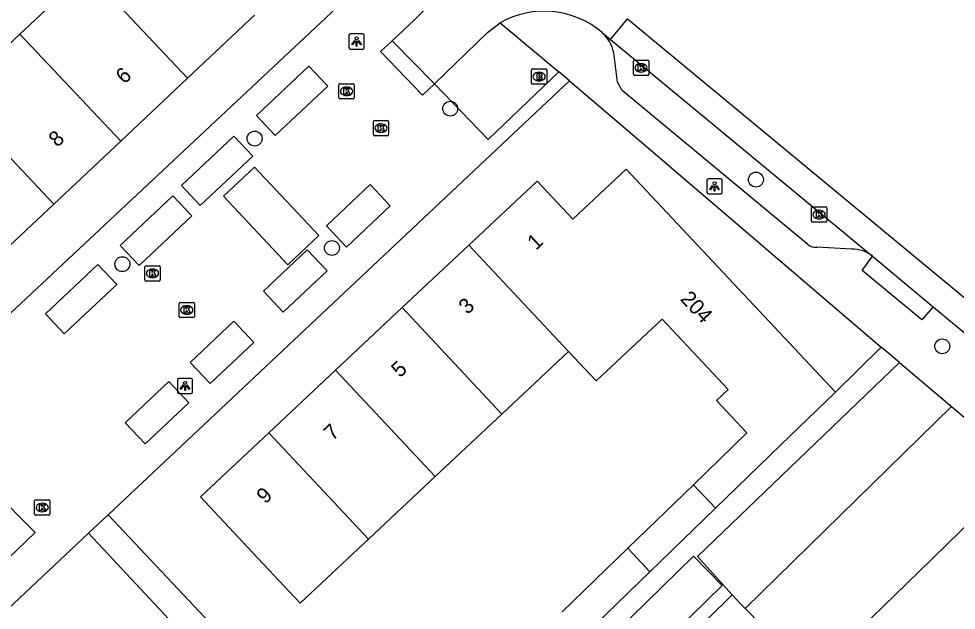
# Model space of a CAD drawing. Extents: x 161882 to 162509, y 381687 to 382379.
# Drawn here: x 162409.8 to 162471.3, y 381838.9 to 381877.6 of the extents above; entities that cross this region are included whole.
import ezdxf

# ---------------------------------------------------------------- set-up
doc = ezdxf.new("R2010")
doc.units = 0
for name, color, linetype in [('IMGEO_Boom', 7, 'Continuous'), ('IMGEO_Brandkraan', 7, 'Continuous'), ('IMGEO_Fietspad_gesloten', 7, 'Continuous'), ('IMGEO_Kolk', 7, 'Continuous'), ('IMGEO_Lichtpunt', 7, 'Continuous'), ('IMGEO_Muur', 7, 'Continuous'), ('IMGEO_Pand', 7, 'Continuous'), ('IMGEO_Pand_nummerreeks', 7, 'Continuous'), ('IMGEO_Parkeervlak_open', 7, 'Continuous'), ('IMGEO_Rijbaan_lokaal_open', 7, 'Continuous'), ('IMGEO_Voetpad_open', 7, 'Continuous')]:
    doc.layers.add(name, color=color, linetype=linetype)

msp = doc.modelspace()

# ---------------------------------------------------------------- linework, layer by layer
at = {"layer": 'IMGEO_Boom'}
for centre in [(162438.129, 381871.741), (162425.306, 381869.781), (162458.161, 381867.092), (162430.377, 381862.605), (162416.641, 381861.547), (162470.374, 381856.157)]:
    msp.add_circle(centre, 0.489, dxfattribs=at)
at = {"layer": 'IMGEO_Brandkraan'}
for p, q in [((162443.452, 381873.418), (162443.452, 381874.27)), ((162443.527, 381874.344), (162444.379, 381874.344)), ((162443.94, 381874.124), (162443.965, 381874.124)), ((162444.453, 381874.27), (162444.453, 381873.418)), ((162444.379, 381873.344), (162443.527, 381873.344)), ((162443.963, 381873.564), (162443.938, 381873.564))]:
    msp.add_line(p, q, dxfattribs=at)
for points in [[(162443.452, 381873.418), (162443.452, 381874.27)], [(162443.527, 381874.344), (162444.379, 381874.344)], [(162443.8, 381874.044), (162443.8, 381873.644), (162444.013, 381873.644)], [(162444.031, 381874.044), (162443.8, 381874.044)], [(162443.979, 381873.963), (162443.925, 381873.963), (162443.925, 381873.887)], [(162443.925, 381873.887), (162443.978, 381873.887)], [(162443.987, 381873.811), (162443.925, 381873.811), (162443.925, 381873.73)], [(162444.453, 381874.27), (162444.453, 381873.418)], [(162444.379, 381873.344), (162443.527, 381873.344)], [(162443.925, 381873.73), (162443.987, 381873.73)]]:
    msp.add_lwpolyline(points, dxfattribs=at)
for centre, radius, start, end in [((162443.529, 381874.268), 0.0765, 91.55205, 178.44795), ((162443.529, 381874.268), 0.0765, 91.55205, 178.44795), ((162443.98, 381873.925), 0.0379, 267.82845, 90.93552), ((162443.988, 381873.77), 0.0404, 269.87594, 90.50774), ((162444.035, 381873.899), 0.145, 59.4692, 91.53667), ((162444.06, 381873.946), 0.0922, 285.51372, 58.15012), ((162444.065, 381873.754), 0.105, 301.31148, 78.98903), ((162444.377, 381874.268), 0.0765, 1.55205, 88.44795), ((162444.377, 381874.268), 0.0765, 1.55205, 88.44795), ((162443.529, 381873.42), 0.0765, 181.55205, 268.44795), ((162443.529, 381873.42), 0.0765, 181.55205, 268.44795), ((162444.019, 381873.895), 0.251, 268.66757, 293.53466), ((162444.377, 381873.42), 0.0765, 271.55205, 358.44795), ((162444.377, 381873.42), 0.0765, 271.55205, 358.44795)]:
    msp.add_arc(centre, radius, start, end, dxfattribs=at)
for centre, major_axis, ratio, start_param, end_param in [((162443.939, 381873.844), (-0.387, 0.002), 0.722429, 4.712389, 7.853982), ((162443.964, 381873.844), (-0.39, 0.002), 0.717154, 1.570796, 4.712389)]:
    msp.add_ellipse(centre, major_axis=major_axis, ratio=ratio, start_param=start_param, end_param=end_param, dxfattribs=at)
at = {"layer": 'IMGEO_Fietspad_gesloten'}
for points in [[(162448.641, 381876.269), (162465.814, 381862.06)], [(162465.814, 381862.06), (162469.781, 381858.758)], [(162469.781, 381858.758), (162474.835, 381854.567)]]:
    msp.add_lwpolyline(points, dxfattribs=at)
at = {"layer": 'IMGEO_Kolk'}
for p, q in [((162450.133, 381873.994), (162450.133, 381874.846)), ((162450.208, 381874.92), (162451.06, 381874.92)), ((162450.621, 381874.7), (162450.646, 381874.7)), ((162451.134, 381874.846), (162451.134, 381873.994)), ((162451.06, 381873.92), (162450.208, 381873.92)), ((162450.644, 381874.14), (162450.619, 381874.14)), ((162430.835, 381872.454), (162430.835, 381873.306)), ((162430.91, 381873.38), (162431.762, 381873.38)), ((162431.836, 381873.306), (162431.836, 381872.454)), ((162431.346, 381872.6), (162431.321, 381872.6)), ((162431.323, 381873.16), (162431.348, 381873.16)), ((162431.762, 381872.38), (162430.91, 381872.38)), ((162433.092, 381870.04), (162433.092, 381870.892)), ((162433.167, 381870.966), (162434.019, 381870.966)), ((162433.58, 381870.746), (162433.605, 381870.746)), ((162434.093, 381870.892), (162434.093, 381870.04)), ((162433.603, 381870.186), (162433.578, 381870.186)), ((162434.019, 381869.966), (162433.167, 381869.966)), ((162461.804, 381864.37), (162461.804, 381865.222)), ((162461.879, 381865.296), (162462.731, 381865.296)), ((162462.805, 381865.222), (162462.805, 381864.37)), ((162462.292, 381865.076), (162462.317, 381865.076)), ((162462.731, 381864.296), (162461.879, 381864.296)), ((162462.315, 381864.516), (162462.29, 381864.516)), ((162418.117, 381860.516), (162418.117, 381861.368)), ((162418.192, 381861.442), (162419.044, 381861.442)), ((162418.605, 381861.222), (162418.63, 381861.222)), ((162419.118, 381861.368), (162419.118, 381860.516)), ((162419.044, 381860.442), (162418.192, 381860.442)), ((162418.628, 381860.662), (162418.603, 381860.662)), ((162420.436, 381859.042), (162421.288, 381859.042)), ((162420.361, 381858.116), (162420.361, 381858.968)), ((162420.849, 381858.822), (162420.874, 381858.822)), ((162421.362, 381858.968), (162421.362, 381858.116)), ((162421.288, 381858.042), (162420.436, 381858.042)), ((162420.872, 381858.262), (162420.847, 381858.262)), ((162410.889, 381845.168), (162410.889, 381846.02)), ((162410.964, 381846.094), (162411.816, 381846.094)), ((162411.377, 381845.874), (162411.402, 381845.874)), ((162411.89, 381846.02), (162411.89, 381845.168)), ((162411.816, 381845.094), (162410.964, 381845.094)), ((162411.4, 381845.314), (162411.375, 381845.314))]:
    msp.add_line(p, q, dxfattribs=at)
for points in [[(162450.133, 381873.994), (162450.133, 381874.846)], [(162450.208, 381874.92), (162451.06, 381874.92)], [(162450.454, 381874.62), (162450.577, 381874.62), (162450.577, 381874.469), (162450.707, 381874.62), (162450.871, 381874.62), (162450.725, 381874.469), (162450.878, 381874.22), (162450.726, 381874.22), (162450.641, 381874.384), (162450.577, 381874.317), (162450.577, 381874.22), (162450.454, 381874.22), (162450.454, 381874.62)], [(162451.134, 381874.846), (162451.134, 381873.994)], [(162451.06, 381873.92), (162450.208, 381873.92)], [(162430.835, 381872.454), (162430.835, 381873.306)], [(162430.91, 381873.38), (162431.762, 381873.38)], [(162431.836, 381873.306), (162431.836, 381872.454)], [(162431.156, 381873.08), (162431.279, 381873.08), (162431.279, 381872.929), (162431.409, 381873.08), (162431.573, 381873.08), (162431.427, 381872.929), (162431.58, 381872.68), (162431.428, 381872.68), (162431.343, 381872.844), (162431.279, 381872.777), (162431.279, 381872.68), (162431.156, 381872.68), (162431.156, 381873.08)], [(162431.762, 381872.38), (162430.91, 381872.38)], [(162433.092, 381870.04), (162433.092, 381870.892)], [(162433.167, 381870.966), (162434.019, 381870.966)], [(162434.093, 381870.892), (162434.093, 381870.04)], [(162433.413, 381870.666), (162433.536, 381870.666), (162433.536, 381870.515), (162433.666, 381870.666), (162433.83, 381870.666), (162433.684, 381870.515), (162433.837, 381870.266), (162433.685, 381870.266), (162433.6, 381870.43), (162433.536, 381870.363), (162433.536, 381870.266), (162433.413, 381870.266), (162433.413, 381870.666)], [(162434.019, 381869.966), (162433.167, 381869.966)], [(162461.804, 381864.37), (162461.804, 381865.222)], [(162461.879, 381865.296), (162462.731, 381865.296)], [(162462.805, 381865.222), (162462.805, 381864.37)], [(162462.125, 381864.996), (162462.248, 381864.996), (162462.248, 381864.845), (162462.378, 381864.996), (162462.542, 381864.996), (162462.396, 381864.845), (162462.549, 381864.596), (162462.397, 381864.596), (162462.312, 381864.76), (162462.248, 381864.693), (162462.248, 381864.596), (162462.125, 381864.596), (162462.125, 381864.996)], [(162462.731, 381864.296), (162461.879, 381864.296)], [(162418.117, 381860.516), (162418.117, 381861.368)], [(162418.192, 381861.442), (162419.044, 381861.442)], [(162418.438, 381861.142), (162418.561, 381861.142), (162418.561, 381860.991), (162418.691, 381861.142), (162418.855, 381861.142), (162418.709, 381860.991), (162418.862, 381860.742), (162418.71, 381860.742), (162418.625, 381860.906), (162418.561, 381860.839), (162418.561, 381860.742), (162418.438, 381860.742), (162418.438, 381861.142)], [(162419.118, 381861.368), (162419.118, 381860.516)], [(162419.044, 381860.442), (162418.192, 381860.442)], [(162420.436, 381859.042), (162421.288, 381859.042)], [(162420.361, 381858.116), (162420.361, 381858.968)], [(162420.682, 381858.742), (162420.805, 381858.742), (162420.805, 381858.591), (162420.935, 381858.742), (162421.099, 381858.742), (162420.953, 381858.591), (162421.106, 381858.342), (162420.954, 381858.342), (162420.869, 381858.506), (162420.805, 381858.439), (162420.805, 381858.342), (162420.682, 381858.342), (162420.682, 381858.742)], [(162421.362, 381858.968), (162421.362, 381858.116)], [(162421.288, 381858.042), (162420.436, 381858.042)], [(162410.889, 381845.168), (162410.889, 381846.02)], [(162410.964, 381846.094), (162411.816, 381846.094)], [(162411.21, 381845.794), (162411.333, 381845.794), (162411.333, 381845.643), (162411.463, 381845.794), (162411.627, 381845.794), (162411.481, 381845.643), (162411.634, 381845.394), (162411.482, 381845.394), (162411.397, 381845.558), (162411.333, 381845.491), (162411.333, 381845.394), (162411.21, 381845.394), (162411.21, 381845.794)], [(162411.89, 381846.02), (162411.89, 381845.168)], [(162411.816, 381845.094), (162410.964, 381845.094)]]:
    msp.add_lwpolyline(points, dxfattribs=at)
for centre, start, end in [((162450.21, 381874.844), 91.55205, 178.44795), ((162450.21, 381874.844), 91.55205, 178.44795), ((162451.058, 381874.844), 1.55205, 88.44795), ((162451.058, 381874.844), 1.55205, 88.44795), ((162450.21, 381873.996), 181.55205, 268.44795), ((162450.21, 381873.996), 181.55205, 268.44795), ((162451.058, 381873.996), 271.55205, 358.44795), ((162451.058, 381873.996), 271.55205, 358.44795), ((162430.912, 381873.304), 91.55205, 178.44795), ((162430.912, 381873.304), 91.55205, 178.44795), ((162431.76, 381873.304), 1.55205, 88.44795), ((162431.76, 381873.304), 1.55205, 88.44795), ((162430.912, 381872.456), 181.55205, 268.44795), ((162430.912, 381872.456), 181.55205, 268.44795), ((162431.76, 381872.456), 271.55205, 358.44795), ((162431.76, 381872.456), 271.55205, 358.44795), ((162433.169, 381870.89), 91.55205, 178.44795), ((162433.169, 381870.89), 91.55205, 178.44795), ((162434.017, 381870.89), 1.55205, 88.44795), ((162434.017, 381870.89), 1.55205, 88.44795), ((162433.169, 381870.042), 181.55205, 268.44795), ((162433.169, 381870.042), 181.55205, 268.44795), ((162434.017, 381870.042), 271.55205, 358.44795), ((162434.017, 381870.042), 271.55205, 358.44795), ((162461.881, 381865.22), 91.55205, 178.44795), ((162461.881, 381865.22), 91.55205, 178.44795), ((162462.729, 381865.22), 1.55205, 88.44795), ((162462.729, 381865.22), 1.55205, 88.44795), ((162461.881, 381864.372), 181.55205, 268.44795), ((162461.881, 381864.372), 181.55205, 268.44795), ((162462.729, 381864.372), 271.55205, 358.44795), ((162462.729, 381864.372), 271.55205, 358.44795), ((162418.194, 381861.366), 91.55205, 178.44795), ((162418.194, 381861.366), 91.55205, 178.44795), ((162419.042, 381861.366), 1.55205, 88.44795), ((162419.042, 381861.366), 1.55205, 88.44795), ((162418.194, 381860.518), 181.55205, 268.44795), ((162418.194, 381860.518), 181.55205, 268.44795), ((162419.042, 381860.518), 271.55205, 358.44795), ((162419.042, 381860.518), 271.55205, 358.44795), ((162420.438, 381858.966), 91.55205, 178.44795), ((162420.438, 381858.966), 91.55205, 178.44795), ((162421.286, 381858.966), 1.55205, 88.44795), ((162421.286, 381858.966), 1.55205, 88.44795), ((162420.438, 381858.118), 181.55205, 268.44795), ((162420.438, 381858.118), 181.55205, 268.44795), ((162421.286, 381858.118), 271.55205, 358.44795), ((162421.286, 381858.118), 271.55205, 358.44795), ((162410.966, 381846.018), 91.55205, 178.44795), ((162410.966, 381846.018), 91.55205, 178.44795), ((162411.814, 381846.018), 1.55205, 88.44795), ((162411.814, 381846.018), 1.55205, 88.44795), ((162410.966, 381845.17), 181.55205, 268.44795), ((162410.966, 381845.17), 181.55205, 268.44795), ((162411.814, 381845.17), 271.55205, 358.44795), ((162411.814, 381845.17), 271.55205, 358.44795)]:
    msp.add_arc(centre, 0.0765, start, end, dxfattribs=at)
for centre, major_axis, ratio, start_param, end_param in [((162450.62, 381874.42), (-0.387, 0.002), 0.722429, 4.712389, 7.853982), ((162450.645, 381874.42), (-0.39, 0.002), 0.717154, 1.570796, 4.712389), ((162431.322, 381872.88), (-0.387, 0.002), 0.722429, 4.712389, 7.853982), ((162431.347, 381872.88), (-0.39, 0.002), 0.717154, 1.570796, 4.712389), ((162433.579, 381870.466), (-0.387, 0.002), 0.722429, 4.712389, 7.853982), ((162433.604, 381870.466), (-0.39, 0.002), 0.717154, 1.570796, 4.712389), ((162462.291, 381864.796), (-0.387, 0.002), 0.722429, 4.712389, 7.853982), ((162462.316, 381864.796), (-0.39, 0.002), 0.717154, 1.570796, 4.712389), ((162418.604, 381860.942), (-0.387, 0.002), 0.722429, 4.712389, 7.853982), ((162418.629, 381860.942), (-0.39, 0.002), 0.717154, 1.570796, 4.712389), ((162420.848, 381858.542), (-0.387, 0.002), 0.722429, 4.712389, 7.853982), ((162420.873, 381858.542), (-0.39, 0.002), 0.717154, 1.570796, 4.712389), ((162411.376, 381845.594), (-0.387, 0.002), 0.722429, 4.712389, 7.853982), ((162411.401, 381845.594), (-0.39, 0.002), 0.717154, 1.570796, 4.712389)]:
    msp.add_ellipse(centre, major_axis=major_axis, ratio=ratio, start_param=start_param, end_param=end_param, dxfattribs=at)
at = {"layer": 'IMGEO_Lichtpunt'}
for p, q in [((162431.493, 381876.552), (162431.493, 381875.745)), ((162431.493, 381876.552), (162431.493, 381875.745)), ((162432.395, 381876.647), (162431.587, 381876.647)), ((162432.395, 381876.647), (162431.587, 381876.647)), ((162432.489, 381875.745), (162432.489, 381876.552)), ((162432.489, 381875.745), (162432.489, 381876.552)), ((162431.587, 381875.651), (162432.395, 381875.651)), ((162431.587, 381875.651), (162432.395, 381875.651)), ((162454.954, 381867.049), (162454.954, 381866.242)), ((162454.954, 381867.049), (162454.954, 381866.242)), ((162455.856, 381867.144), (162455.048, 381867.144)), ((162455.856, 381867.144), (162455.048, 381867.144)), ((162455.95, 381866.242), (162455.95, 381867.049)), ((162455.95, 381866.242), (162455.95, 381867.049)), ((162455.048, 381866.148), (162455.856, 381866.148)), ((162455.048, 381866.148), (162455.856, 381866.148)), ((162420.249, 381853.963), (162420.249, 381853.156)), ((162420.249, 381853.963), (162420.249, 381853.156)), ((162421.151, 381854.058), (162420.343, 381854.058)), ((162421.151, 381854.058), (162420.343, 381854.058)), ((162421.245, 381853.156), (162421.245, 381853.963)), ((162421.245, 381853.156), (162421.245, 381853.963)), ((162420.343, 381853.062), (162421.151, 381853.062)), ((162420.343, 381853.062), (162421.151, 381853.062))]:
    msp.add_line(p, q, dxfattribs=at)
for points in [[(162431.867, 381876.216), (162431.906, 381876.188), (162431.718, 381875.926), (162431.68, 381875.953), (162431.867, 381876.216)], [(162431.969, 381876.168), (162432.016, 381876.168), (162432.016, 381875.846), (162431.969, 381875.846), (162431.969, 381876.168)], [(162432.079, 381876.188), (162432.117, 381876.215), (162432.304, 381875.953), (162432.265, 381875.925), (162432.079, 381876.188)], [(162455.328, 381866.713), (162455.367, 381866.685), (162455.179, 381866.423), (162455.141, 381866.45), (162455.328, 381866.713)], [(162455.43, 381866.665), (162455.477, 381866.665), (162455.477, 381866.343), (162455.43, 381866.343), (162455.43, 381866.665)], [(162455.54, 381866.685), (162455.578, 381866.712), (162455.765, 381866.45), (162455.726, 381866.422), (162455.54, 381866.685)], [(162420.623, 381853.627), (162420.662, 381853.599), (162420.474, 381853.337), (162420.436, 381853.364), (162420.623, 381853.627)], [(162420.725, 381853.579), (162420.772, 381853.579), (162420.772, 381853.257), (162420.725, 381853.257), (162420.725, 381853.579)], [(162420.835, 381853.599), (162420.873, 381853.626), (162421.06, 381853.364), (162421.021, 381853.336), (162420.835, 381853.599)]]:
    msp.add_lwpolyline(points, dxfattribs=at)
for centre in [(162431.992, 381876.35), (162455.453, 381866.847), (162420.748, 381853.761)]:
    msp.add_circle(centre, 0.0994, dxfattribs=at)
for centre, start, end in [((162431.587, 381876.552), 90, 180), ((162431.587, 381876.552), 90, 180), ((162432.395, 381876.552), 0, 90), ((162432.395, 381876.552), 0, 90), ((162431.587, 381875.745), 180, 270), ((162431.587, 381875.745), 180, 270), ((162432.395, 381875.745), 270, 0), ((162432.395, 381875.745), 270, 360), ((162455.048, 381867.049), 90, 180), ((162455.048, 381867.049), 90, 180), ((162455.856, 381867.049), 0, 90), ((162455.856, 381867.049), 0, 90), ((162455.048, 381866.242), 180, 270), ((162455.048, 381866.242), 180, 270), ((162455.856, 381866.242), 270, 0), ((162455.856, 381866.242), 270, 360), ((162420.343, 381853.963), 90, 180), ((162420.343, 381853.963), 90, 180), ((162421.151, 381853.963), 0, 90), ((162421.151, 381853.963), 0, 90), ((162420.343, 381853.156), 180, 270), ((162420.343, 381853.156), 180, 270), ((162421.151, 381853.156), 270, 0), ((162421.151, 381853.156), 270, 360)]:
    msp.add_arc(centre, 0.0946, start, end, dxfattribs=at)
at = {"layer": 'IMGEO_Muur'}
msp.add_lwpolyline([(162451.124, 381869.144), (162466.37, 381856.1)], dxfattribs=at)
at = {"layer": 'IMGEO_Pand'}
for points in [[(162414.306, 381880.758), (162409.922, 381876.629)], [(162420.917, 381873.749), (162414.306, 381880.758)], [(162420.917, 381873.749), (162425.301, 381877.878)], [(162409.922, 381876.629), (162405.536, 381872.499)], [(162409.922, 381876.629), (162416.532, 381869.62)], [(162416.532, 381869.62), (162420.917, 381873.749)], [(162412.146, 381865.49), (162405.536, 381872.499)], [(162412.146, 381865.49), (162416.532, 381869.62)], [(162463.374, 381853.157), (162449.668, 381867.778), (162446.174, 381864.501), (162443.836, 381866.995), (162439.353, 381862.793)], [(162407.762, 381861.361), (162412.146, 381865.49)], [(162439.353, 381862.793), (162434.982, 381858.694)], [(162445.888, 381855.818), (162439.353, 381862.793)], [(162434.982, 381858.694), (162430.609, 381854.595)], [(162434.982, 381858.694), (162441.516, 381851.719)], [(162445.888, 381855.818), (162447.693, 381853.892), (162452.009, 381857.938), (162456.334, 381853.324), (162455.577, 381852.614), (162457.572, 381850.485), (162454.068, 381847.088)], [(162441.516, 381851.719), (162445.888, 381855.818)], [(162430.609, 381854.595), (162426.237, 381850.496)], [(162437.144, 381847.62), (162430.609, 381854.595)], [(162463.374, 381853.157), (162459.784, 381849.678), (162455.517, 381845.542)], [(162437.144, 381847.62), (162441.516, 381851.719)], [(162426.237, 381850.496), (162421.754, 381846.293), (162425.173, 381842.645), (162428.291, 381839.32), (162432.772, 381843.521)], [(162426.237, 381850.496), (162432.772, 381843.521)], [(162432.772, 381843.521), (162437.144, 381847.62)], [(162449.764, 381842.916), (162454.068, 381847.088)], [(162454.068, 381847.088), (162455.517, 381845.542)], [(162455.517, 381845.542), (162451.213, 381841.37)], [(162461.809, 381834.525), (162468.874, 381841.412), (162472.454, 381844.902), (162474.369, 381842.947)], [(162445.46, 381838.744), (162449.764, 381842.916)], [(162449.764, 381842.916), (162451.213, 381841.37)], [(162444.862, 381833.372), (162454.078, 381842.393), (162455.959, 381840.477), (162446.742, 381831.455)], [(162451.213, 381841.37), (162446.909, 381837.198)]]:
    msp.add_lwpolyline(points, dxfattribs=at)
at = {"layer": 'IMGEO_Parkeervlak_open'}
msp.add_lwpolyline([(162456.614, 381839.875), (162457.182, 381839.251), (162457.462, 381838.965)], dxfattribs=at)
at = {"layer": 'IMGEO_Rijbaan_lokaal_open'}
for points in [[(162435.163, 381882.568), (162392.054, 381842.176)], [(162437.462, 381879.298), (162435.764, 381877.534), (162434.327, 381876.199)], [(162448.641, 381876.269), (162449.745, 381877.636), (162472.8, 381858.554)], [(162437.088, 381873.372), (162440.581, 381876.745), (162441.399, 381877.367)], [(162448.077, 381876.736), (162448.641, 381876.269)], [(162437.088, 381873.372), (162436.317, 381872.624), (162433.548, 381875.489), (162434.327, 381876.199)], [(162434.327, 381876.199), (162437.088, 381873.372)], [(162426.659, 381869.982), (162425.425, 381871.294), (162428.868, 381874.534), (162430.103, 381873.222), (162426.659, 381869.982)], [(162445.243, 381874.161), (162440.624, 381869.71), (162437.088, 381873.372)], [(162445.952, 381873.569), (162445.243, 381874.161)], [(162415.713, 381845.109), (162445.952, 381873.569)], [(162421.745, 381865.394), (162420.511, 381866.706), (162423.955, 381869.946), (162425.189, 381868.634), (162421.745, 381865.394)], [(162423.262, 381866.001), (162425.293, 381867.913), (162429.522, 381863.42), (162427.49, 381861.508), (162423.262, 381866.001)], [(162432.89, 381866.759), (162434.195, 381865.372), (162431.324, 381862.67), (162430.018, 381864.057), (162432.89, 381866.759)], [(162417.74, 381861.466), (162416.506, 381862.778), (162419.95, 381866.018), (162421.184, 381864.706), (162417.74, 381861.466)], [(162428.756, 381862.485), (162430.061, 381861.098), (162427.189, 381858.396), (162425.884, 381859.783), (162428.756, 381862.485)], [(162412.829, 381856.982), (162411.594, 381858.294), (162415.038, 381861.534), (162416.273, 381860.222), (162412.829, 381856.982)], [(162423.956, 381857.804), (162425.262, 381856.417), (162422.39, 381853.715), (162421.085, 381855.102), (162423.956, 381857.804)], [(162416.824, 381851.147), (162419.695, 381853.848), (162421.001, 381852.461), (162418.129, 381849.759), (162416.824, 381851.147)], [(162470.986, 381852.206), (162457.462, 381838.965)], [(162470.986, 381852.206), (162481.416, 381843.4), (162482.294, 381842.465)], [(162406.177, 381841.768), (162404.579, 381843.352), (162408.119, 381846.74), (162410.925, 381843.958), (162407.385, 381840.57)], [(162415.713, 381845.109), (162414.428, 381843.9)], [(162414.428, 381843.9), (162376.404, 381808.113)], [(162457.462, 381838.965), (162461.809, 381834.525)]]:
    msp.add_lwpolyline(points, dxfattribs=at)
msp.add_arc((162444.29, 381872.309), 5.826, 49.45476, 119.74961, dxfattribs=at)
at = {"layer": 'IMGEO_Voetpad_open'}
for points in [[(162441.399, 381877.367), (162445.243, 381874.161)], [(162461.563, 381862.837), (162449.389, 381872.936), (162449.094, 381873.481), (162448.841, 381875.408)], [(162445.952, 381873.569), (162451.124, 381869.144), (162466.37, 381856.1)], [(162464.449, 381862.533), (162462.156, 381862.663)], [(162469.781, 381858.758), (162469.034, 381857.891), (162465.126, 381861.128), (162465.814, 381862.06)], [(162466.37, 381856.1), (162463.374, 381853.157)], [(162467.568, 381855.092), (162466.37, 381856.1)], [(162456.614, 381839.875), (162454.336, 381842.374), (162467.568, 381855.092)], [(162467.568, 381855.092), (162470.986, 381852.206)], [(162430.442, 381829.459), (162415.713, 381845.109)], [(162420.305, 381837.611), (162414.428, 381843.9)], [(162429.518, 381794.561), (162421.052, 381804.384), (162420.873, 381804.592), (162456.614, 381839.875)]]:
    msp.add_lwpolyline(points, dxfattribs=at)
for centre, radius, start, end in [((162446.516, 381874.954), 2.369, 11.04713, 48.77661), ((162462.058, 381863.427), 0.77, 229.99483, 277.29934), ((162464.482, 381860.423), 2.111, 50.87511, 90.90043)]:
    msp.add_arc(centre, radius, start, end, dxfattribs=at)

# ---------------------------------------------------------------- texts
at = {"layer": 'IMGEO_Pand_nummerreeks'}
for s, rotation, p in [('6', 43.28127, (162416.775, 381873.31)), ('8', 43.28127, (162412.38, 381869.171)), ('1', 43.15256, (162443.753, 381862.421)), ('204', 313.19126, (162453.155, 381859.219)), ('3', 43.15256, (162439.254, 381858.203)), ('5', 43.15256, (162434.837, 381854.062)), ('7', 43.15256, (162430.421, 381849.922)), ('9', 43.15256, (162426.005, 381845.782))]:
    msp.add_text(s, height=1, rotation=rotation, dxfattribs=at).set_placement(p)

doc.saveas('drawing.dxf')
